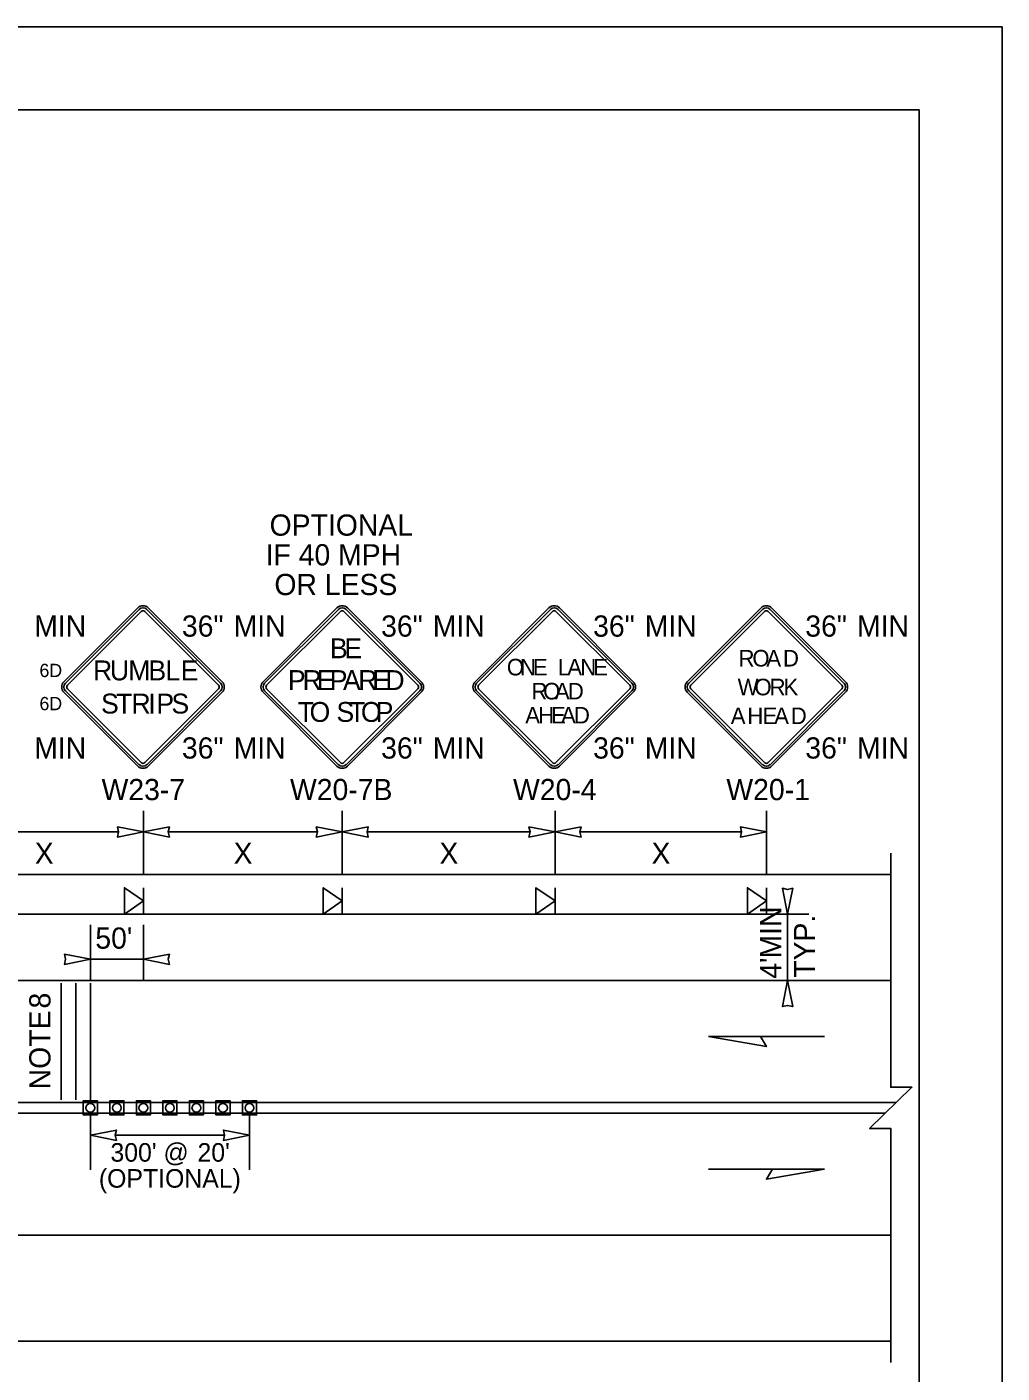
# Model space of a CAD drawing. Extents: x 99999.1 to 100095.7, y 99995 to 100010.7.
# Drawn here: x 100012.38 to 100016.06, y 100005.61 to 100010.69 of the extents above; entities that cross this region are included whole.
import ezdxf

# ---------------------------------------------------------------- set-up
doc = ezdxf.new("R2010")
doc.units = 0
for name, color, linetype in [('RD_ED_ShoulderPavedEdge', 7, 'Continuous'), ('RD_MK_LineDblYellowCenter', 7, 'Continuous'), ('RD_MK_LineEdgeWhite', 7, 'Continuous'), ('SH_GI_PlotLimits', 7, 'Continuous'), ('SH_GI_SheetBorder', 7, 'Continuous'), ('TR_SN_ConstructionSigns', 7, 'Continuous'), ('TR_WZ_PortableSignMountBlk-Org', 7, 'Continuous'), ('TR_WZ_TrafficCone', 7, 'Continuous'), ('TR_WZ_WorkZoneDetails', 7, 'Continuous'), ('TR_WZ_WorkZoneTextCurrent', 7, 'Continuous')]:
    doc.layers.add(name, color=color, linetype=linetype)

msp = doc.modelspace()

# ---------------------------------------------------------------- linework, layer by layer
at = {"layer": 'RD_ED_ShoulderPavedEdge'}
for p, q in [((100000.1076, 100007.4923), (100015.6424, 100007.4923)), ((100000.1076, 100005.7323), (100015.6424, 100005.7323))]:
    msp.add_line(p, q, dxfattribs=at)
at = {"layer": 'RD_MK_LineDblYellowCenter'}
for p, q in [((100012.2733, 100006.6323), (100015.6631, 100006.6323)), ((100012.2733, 100006.5923), (100015.6218, 100006.5923))]:
    msp.add_line(p, q, dxfattribs=at)
at = {"layer": 'RD_MK_LineEdgeWhite'}
for p, q in [((100000.1076, 100007.0923), (100015.6424, 100007.0923)), ((100000.1076, 100006.1323), (100015.6424, 100006.1323))]:
    msp.add_line(p, q, dxfattribs=at)
at = {"layer": 'SH_GI_PlotLimits'}
msp.add_lwpolyline([(99999.0625, 99999.6875), (100016.0625, 99999.6875), (100016.0625, 100010.6875), (99999.0625, 100010.6875)], close=True, dxfattribs=at)
at = {"layer": 'SH_GI_SheetBorder'}
for p, q in [((100000, 100010.375), (100015.75, 100010.375)), ((100015.75, 100010.375), (100015.75, 100000))]:
    msp.add_line(p, q, dxfattribs=at)
at = {"layer": 'TR_SN_ConstructionSigns'}
for p, q in [((100012.8019, 100008.4972), (100012.5235, 100008.2188)), ((100012.8075, 100008.4917), (100012.529, 100008.2132)), ((100013.1146, 100008.2132), (100012.8362, 100008.4917)), ((100013.1201, 100008.2188), (100012.8417, 100008.4972)), ((100013.5535, 100008.4972), (100013.275, 100008.2188)), ((100013.559, 100008.4917), (100013.2806, 100008.2132)), ((100013.8661, 100008.2132), (100013.5877, 100008.4917)), ((100013.8717, 100008.2188), (100013.5932, 100008.4972)), ((100014.3532, 100008.4972), (100014.0747, 100008.2188)), ((100014.3587, 100008.4917), (100014.0803, 100008.2132)), ((100014.6658, 100008.2132), (100014.3874, 100008.4917)), ((100014.6714, 100008.2188), (100014.3929, 100008.4972)), ((100015.1535, 100008.4972), (100014.875, 100008.2188)), ((100015.159, 100008.4917), (100014.8806, 100008.2132)), ((100015.4661, 100008.2132), (100015.1877, 100008.4917)), ((100015.4717, 100008.2188), (100015.1932, 100008.4972)), ((100012.5368, 100008.2055), (100012.8152, 100008.4839)), ((100012.8285, 100008.4839), (100013.1069, 100008.2055)), ((100013.2883, 100008.2055), (100013.5667, 100008.4839)), ((100013.58, 100008.4839), (100013.8584, 100008.2055)), ((100014.088, 100008.2055), (100014.3664, 100008.4839)), ((100014.3797, 100008.4839), (100014.6581, 100008.2055)), ((100014.8883, 100008.2055), (100015.1667, 100008.4839)), ((100015.18, 100008.4839), (100015.4584, 100008.2055)), ((100012.529, 100008.1845), (100012.8075, 100007.9061)), ((100012.8152, 100007.9138), (100012.5368, 100008.1923)), ((100013.1069, 100008.1923), (100012.8285, 100007.9138)), ((100012.8362, 100007.9061), (100013.1146, 100008.1845)), ((100013.2806, 100008.1845), (100013.559, 100007.9061)), ((100013.5667, 100007.9138), (100013.2883, 100008.1923)), ((100013.8584, 100008.1923), (100013.58, 100007.9138)), ((100013.5877, 100007.9061), (100013.8661, 100008.1845)), ((100014.0803, 100008.1845), (100014.3587, 100007.9061)), ((100014.3664, 100007.9138), (100014.088, 100008.1923)), ((100014.6581, 100008.1923), (100014.3797, 100007.9138)), ((100014.3874, 100007.9061), (100014.6658, 100008.1845)), ((100014.8806, 100008.1845), (100015.159, 100007.9061)), ((100015.1667, 100007.9138), (100014.8883, 100008.1923)), ((100015.4584, 100008.1923), (100015.18, 100007.9138)), ((100015.1877, 100007.9061), (100015.4661, 100008.1845)), ((100012.5235, 100008.179), (100012.8019, 100007.9006)), ((100012.8417, 100007.9006), (100013.1201, 100008.179)), ((100013.275, 100008.179), (100013.5535, 100007.9006)), ((100013.5932, 100007.9006), (100013.8717, 100008.179)), ((100014.0747, 100008.179), (100014.3532, 100007.9006)), ((100014.3929, 100007.9006), (100014.6714, 100008.179)), ((100014.875, 100008.179), (100015.1535, 100007.9006)), ((100015.1932, 100007.9006), (100015.4717, 100008.179))]:
    msp.add_line(p, q, dxfattribs=at)
for centre, radius, start, end in [((100012.8218, 100008.4773), 0.0281, 45, 135), ((100012.8218, 100008.4773), 0.0203, 45, 135), ((100013.5733, 100008.4773), 0.0281, 45, 135), ((100013.5733, 100008.4773), 0.0203, 45, 135), ((100014.373, 100008.4773), 0.0281, 45, 135), ((100014.373, 100008.4773), 0.0203, 45, 135), ((100015.1733, 100008.4773), 0.0281, 45, 135), ((100015.1733, 100008.4773), 0.0203, 45, 135), ((100012.8218, 100008.4773), 0.00937, 45, 135), ((100013.5733, 100008.4773), 0.00937, 45, 135), ((100014.373, 100008.4773), 0.00937, 45, 135), ((100015.1733, 100008.4773), 0.00937, 45, 135), ((100012.5434, 100008.1989), 0.0281, 135, 225), ((100012.5434, 100008.1989), 0.0203, 135, 225), ((100012.5434, 100008.1989), 0.00937, 135, 225), ((100013.1003, 100008.1989), 0.00937, 315, 45), ((100013.1003, 100008.1989), 0.0203, 315, 45), ((100013.1003, 100008.1989), 0.0281, 315, 45), ((100013.2949, 100008.1989), 0.0281, 135, 225), ((100013.2949, 100008.1989), 0.0203, 135, 225), ((100013.2949, 100008.1989), 0.00937, 135, 225), ((100013.8518, 100008.1989), 0.00937, 315, 45), ((100013.8518, 100008.1989), 0.0203, 315, 45), ((100013.8518, 100008.1989), 0.0281, 315, 45), ((100014.0946, 100008.1989), 0.0281, 135, 225), ((100014.0946, 100008.1989), 0.0203, 135, 225), ((100014.0946, 100008.1989), 0.00937, 135, 225), ((100014.6515, 100008.1989), 0.00937, 315, 45), ((100014.6515, 100008.1989), 0.0203, 315, 45), ((100014.6515, 100008.1989), 0.0281, 315, 45), ((100014.8949, 100008.1989), 0.0281, 135, 225), ((100014.8949, 100008.1989), 0.0203, 135, 225), ((100014.8949, 100008.1989), 0.00937, 135, 225), ((100015.4518, 100008.1989), 0.00937, 315, 45), ((100015.4518, 100008.1989), 0.0203, 315, 45), ((100015.4518, 100008.1989), 0.0281, 315, 45), ((100012.8218, 100007.9205), 0.0281, 225, 315), ((100012.8218, 100007.9205), 0.0203, 225, 315), ((100012.8218, 100007.9205), 0.00937, 225, 315), ((100013.5733, 100007.9205), 0.0281, 225, 315), ((100013.5733, 100007.9205), 0.0203, 225, 315), ((100013.5733, 100007.9205), 0.00937, 225, 315), ((100014.373, 100007.9205), 0.0281, 225, 315), ((100014.373, 100007.9205), 0.0203, 225, 315), ((100014.373, 100007.9205), 0.00937, 225, 315), ((100015.1733, 100007.9205), 0.0281, 225, 315), ((100015.1733, 100007.9205), 0.0203, 225, 315), ((100015.1733, 100007.9205), 0.00937, 225, 315)]:
    msp.add_arc(centre, radius, start, end, dxfattribs=at)
at = {"layer": 'TR_WZ_PortableSignMountBlk-Org'}
for p, q in [((100012.8233, 100007.4422), (100012.8233, 100007.3422)), ((100013.5733, 100007.4422), (100013.5733, 100007.3422)), ((100014.3761, 100007.4422), (100014.3761, 100007.3422)), ((100015.1733, 100007.4422), (100015.1733, 100007.3422))]:
    msp.add_line(p, q, dxfattribs=at)
for points in [[(100012.8233, 100007.3923), (100012.7515, 100007.3422), (100012.7515, 100007.4422)], [(100013.5733, 100007.3923), (100013.5015, 100007.3422), (100013.5015, 100007.4422)], [(100014.3761, 100007.3923), (100014.3042, 100007.3422), (100014.3042, 100007.4422)], [(100015.1733, 100007.3923), (100015.1015, 100007.3422), (100015.1015, 100007.4422)]]:
    msp.add_lwpolyline(points, close=True, dxfattribs=at)
at = {"layer": 'TR_WZ_TrafficCone'}
for points in [[(100012.65, 100006.5857), (100012.5967, 100006.5857), (100012.5967, 100006.639), (100012.65, 100006.639), (100012.65, 100006.5857)], [(100012.65, 100006.639), (100012.5967, 100006.639), (100012.5967, 100006.5857), (100012.65, 100006.5857), (100012.65, 100006.639)], [(100012.75, 100006.5857), (100012.6967, 100006.5857), (100012.6967, 100006.639), (100012.75, 100006.639), (100012.75, 100006.5857)], [(100012.75, 100006.639), (100012.6967, 100006.639), (100012.6967, 100006.5857), (100012.75, 100006.5857), (100012.75, 100006.639)], [(100012.85, 100006.5857), (100012.7967, 100006.5857), (100012.7967, 100006.639), (100012.85, 100006.639), (100012.85, 100006.5857)], [(100012.85, 100006.639), (100012.7967, 100006.639), (100012.7967, 100006.5857), (100012.85, 100006.5857), (100012.85, 100006.639)], [(100012.95, 100006.5857), (100012.8967, 100006.5857), (100012.8967, 100006.639), (100012.95, 100006.639), (100012.95, 100006.5857)], [(100012.95, 100006.639), (100012.8967, 100006.639), (100012.8967, 100006.5857), (100012.95, 100006.5857), (100012.95, 100006.639)], [(100013.05, 100006.5857), (100012.9967, 100006.5857), (100012.9967, 100006.639), (100013.05, 100006.639), (100013.05, 100006.5857)], [(100013.05, 100006.639), (100012.9967, 100006.639), (100012.9967, 100006.5857), (100013.05, 100006.5857), (100013.05, 100006.639)], [(100013.15, 100006.5857), (100013.0967, 100006.5857), (100013.0967, 100006.639), (100013.15, 100006.639), (100013.15, 100006.5857)], [(100013.15, 100006.639), (100013.0967, 100006.639), (100013.0967, 100006.5857), (100013.15, 100006.5857), (100013.15, 100006.639)], [(100013.25, 100006.5857), (100013.1967, 100006.5857), (100013.1967, 100006.639), (100013.25, 100006.639), (100013.25, 100006.5857)], [(100013.25, 100006.639), (100013.1967, 100006.639), (100013.1967, 100006.5857), (100013.25, 100006.5857), (100013.25, 100006.639)]]:
    msp.add_lwpolyline(points, dxfattribs=at)
for centre in [(100012.6233, 100006.6123), (100012.7233, 100006.6123), (100012.8233, 100006.6123), (100012.9233, 100006.6123), (100013.0233, 100006.6123), (100013.1233, 100006.6123), (100013.2233, 100006.6123)]:
    msp.add_circle(centre, 0.0167, dxfattribs=at)
at = {"layer": 'TR_WZ_WorkZoneDetails'}
for p, q in [((100012.8233, 100007.4923), (100012.8233, 100007.7323)), ((100013.5733, 100007.4923), (100013.5733, 100007.7323)), ((100014.3761, 100007.4923), (100014.3761, 100007.7323)), ((100015.1733, 100007.4921), (100015.1733, 100007.7323)), ((100012.1671, 100007.6523), (100012.7296, 100007.6523)), ((100012.9171, 100007.6523), (100013.4796, 100007.6523)), ((100013.6671, 100007.6523), (100014.2823, 100007.6523)), ((100014.4698, 100007.6523), (100015.0796, 100007.6523)), ((100012.0733, 100007.3422), (100015.1733, 100007.3422)), ((100015.1733, 100007.3422), (100015.3333, 100007.3422)), ((100015.2533, 100007.3422), (100015.2533, 100007.0923)), ((100012.6233, 100007.0923), (100012.6233, 100007.3023)), ((100012.8233, 100007.3023), (100012.8233, 100007.0923)), ((100012.6233, 100007.1723), (100012.8233, 100007.1723)), ((100012.5128, 100006.6423), (100012.5128, 100007.0823)), ((100012.5685, 100006.6423), (100012.5685, 100007.0823)), ((100012.6233, 100006.6423), (100012.6233, 100007.0823)), ((100015.1733, 100007.0923), (100015.3333, 100007.0923)), ((100015.1513, 100006.8816), (100015.3924, 100006.8816)), ((100012.6233, 100006.589), (100012.6233, 100006.379)), ((100013.2233, 100006.379), (100013.2233, 100006.589)), ((100013.1296, 100006.509), (100012.7171, 100006.509)), ((100015.1959, 100006.3816), (100014.9548, 100006.3816))]:
    msp.add_line(p, q, dxfattribs=at)
for points in [[(100012.8233, 100007.6523), (100012.7251, 100007.6331), (100012.7296, 100007.6523), (100012.7251, 100007.6716)], [(100012.8233, 100007.6523), (100012.9216, 100007.6331), (100012.9171, 100007.6523), (100012.9216, 100007.6716)], [(100013.5733, 100007.6523), (100013.4751, 100007.6331), (100013.4796, 100007.6523), (100013.4751, 100007.6716)], [(100013.5733, 100007.6523), (100013.6716, 100007.6331), (100013.6671, 100007.6523), (100013.6716, 100007.6716)], [(100014.3761, 100007.6523), (100014.2778, 100007.6331), (100014.2823, 100007.6523), (100014.2778, 100007.6716)], [(100014.3761, 100007.6523), (100014.4743, 100007.6331), (100014.4698, 100007.6523), (100014.4743, 100007.6716)], [(100015.1733, 100007.6523), (100015.0751, 100007.6331), (100015.0796, 100007.6523), (100015.0751, 100007.6716)], [(100015.2533, 100007.3422), (100015.2341, 100007.4405), (100015.2533, 100007.436), (100015.2726, 100007.4405)], [(100012.6233, 100007.1723), (100012.5251, 100007.1916), (100012.5296, 100007.1723), (100012.5251, 100007.1531)], [(100012.8233, 100007.1723), (100012.9216, 100007.1916), (100012.9171, 100007.1723), (100012.9216, 100007.1531)], [(100015.2533, 100007.0923), (100015.2341, 100006.9941), (100015.2533, 100006.9986), (100015.2726, 100006.9941)], [(100014.9548, 100006.8816), (100015.1736, 100006.843), (100015.1513, 100006.8816)], [(100012.6233, 100006.509), (100012.7216, 100006.4897), (100012.7171, 100006.509), (100012.7216, 100006.5283)], [(100013.2233, 100006.509), (100013.1251, 100006.4897), (100013.1296, 100006.509), (100013.1251, 100006.5283)], [(100015.3924, 100006.3816), (100015.1736, 100006.343), (100015.1959, 100006.3816)]]:
    msp.add_lwpolyline(points, close=True, dxfattribs=at)
msp.add_lwpolyline([(100015.6424, 100005.6523), (100015.6424, 100006.5349), (100015.5624, 100006.5349), (100015.7225, 100006.6898), (100015.6424, 100006.6898), (100015.6424, 100007.5723)], dxfattribs=at)

# ---------------------------------------------------------------- texts
at = {"layer": 'TR_SN_ConstructionSigns'}
for s, height, p in [('OPTIONAL', 0.08, (100013.2994, 100008.7694)), ('IF 40 MPH', 0.08, (100013.2843, 100008.6574)), ('OR LESS', 0.08, (100013.3175, 100008.5454)), ('B', 0.075, (100013.5271, 100008.3074)), ('E', 0.075, (100013.5814, 100008.3074)), ('R', 0.0625, (100015.0683, 100008.2762)), ('O', 0.0625, (100015.1204, 100008.2762)), ('A', 0.0625, (100015.1732, 100008.2762)), ('D', 0.0625, (100015.2359, 100008.2762)), ('6D', 0.05, (100012.4313, 100008.2364)), ('R', 0.075, (100012.6332, 100008.2239)), ('U', 0.075, (100012.697, 100008.2239)), ('M', 0.075, (100012.766, 100008.2239)), ('B', 0.075, (100012.8425, 100008.2239)), ('L', 0.075, (100012.9062, 100008.2239)), ('E', 0.075, (100012.964, 100008.2239)), ('O', 0.0625, (100014.1943, 100008.2426)), ('N', 0.0625, (100014.2437, 100008.2426)), ('E', 0.0625, (100014.2924, 100008.2426)), ('L', 0.0625, (100014.3868, 100008.2426)), ('A', 0.0625, (100014.4224, 100008.2426)), ('N', 0.0625, (100014.4712, 100008.2426)), ('E', 0.0625, (100014.5199, 100008.2426)), ('P', 0.075, (100013.3684, 100008.1874)), ('R', 0.075, (100013.4237, 100008.1874)), ('E', 0.075, (100013.4769, 100008.1874)), ('P', 0.075, (100013.5264, 100008.1874)), ('A', 0.075, (100013.5763, 100008.1874)), ('R', 0.075, (100013.6335, 100008.1874)), ('E', 0.075, (100013.6868, 100008.1874)), ('D', 0.075, (100013.7362, 100008.1874)), ('R', 0.0625, (100014.2868, 100008.152)), ('O', 0.0625, (100014.3312, 100008.152)), ('A', 0.0625, (100014.3755, 100008.152)), ('D', 0.0625, (100014.4243, 100008.152)), ('W', 0.0625, (100015.065, 100008.1676)), ('O', 0.0625, (100015.1282, 100008.1676)), ('R', 0.0625, (100015.1855, 100008.1676)), ('K', 0.0625, (100015.2379, 100008.1676)), ('6D', 0.05, (100012.4313, 100008.1114)), ('S', 0.075, (100012.6636, 100008.0989)), ('T', 0.075, (100012.7206, 100008.0989)), ('R', 0.075, (100012.7783, 100008.0989)), ('I', 0.075, (100012.8421, 100008.0989)), ('P', 0.075, (100012.8721, 100008.0989)), ('S', 0.075, (100012.9291, 100008.0989)), ('T', 0.075, (100013.4051, 100008.0674)), ('O', 0.075, (100013.4502, 100008.0674)), ('S', 0.075, (100013.5516, 100008.0674)), ('T', 0.075, (100013.5988, 100008.0674)), ('O', 0.075, (100013.6439, 100008.0674)), ('P', 0.075, (100013.6996, 100008.0674)), ('A', 0.0625, (100014.2637, 100008.0614)), ('H', 0.0625, (100014.3124, 100008.0614)), ('E', 0.0625, (100014.3612, 100008.0614)), ('A', 0.0625, (100014.3987, 100008.0614)), ('D', 0.0625, (100014.4474, 100008.0614)), ('A', 0.0625, (100015.039, 100008.0591)), ('H', 0.0625, (100015.1015, 100008.0591)), ('E', 0.0625, (100015.159, 100008.0591)), ('A', 0.0625, (100015.2027, 100008.0591)), ('D', 0.0625, (100015.2652, 100008.0591))]:
    msp.add_text(s, height=height, dxfattribs=at).set_placement(p)
for s, p in [('MIN', (100012.4114, 100008.3887)), ('36"', (100012.9686, 100008.3887)), ('MIN', (100013.1636, 100008.3887)), ('36"', (100013.7201, 100008.3887)), ('MIN', (100013.9151, 100008.3887)), ('36"', (100014.5198, 100008.3887)), ('MIN', (100014.7148, 100008.3887)), ('36"', (100015.3201, 100008.3887)), ('MIN', (100015.5151, 100008.3887)), ('MIN', (100012.4114, 100007.9291)), ('36"', (100012.9686, 100007.9291)), ('MIN', (100013.1636, 100007.9291)), ('36"', (100013.7201, 100007.9291)), ('MIN', (100013.9151, 100007.9291)), ('36"', (100014.5198, 100007.9291)), ('MIN', (100014.7148, 100007.9291)), ('36"', (100015.3201, 100007.9291)), ('MIN', (100015.5151, 100007.9291)), ('W23-7', (100012.6656, 100007.7723)), ('W20-7B', (100013.3763, 100007.7723)), ('W20-4', (100014.2176, 100007.7723)), ('W20-1', (100015.0224, 100007.7723))]:
    msp.add_text(s, height=0.08, rotation=360, dxfattribs=at).set_placement(p)
at = {"layer": 'TR_WZ_WorkZoneDetails'}
for s, p in [('8', (100012.4728, 100006.9868)), ('NOTE', (100012.4728, 100006.682))]:
    msp.add_text(s, height=0.08, rotation=90, dxfattribs=at).set_placement(p)
at = {"layer": 'TR_WZ_WorkZoneTextCurrent'}
for s, height, p in [('X', 0.08, (100012.4136, 100007.5323)), ('X', 0.08, (100013.1636, 100007.5323)), ('X', 0.08, (100013.94, 100007.5323)), ('X', 0.08, (100014.74, 100007.5323)), ("50'", 0.08, (100012.6421, 100007.2123)), ("300' @", 0.07, (100012.699, 100006.4093)), ("20'", 0.07, (100013.0274, 100006.4093)), ('(OPTIONAL)', 0.07, (100012.6553, 100006.3113))]:
    msp.add_text(s, height=height, dxfattribs=at).set_placement(p)
for s, p in [('MIN', (100015.2293, 100007.1754)), ('TYP.', (100015.3573, 100007.1026)), ("4'", (100015.2293, 100007.0989))]:
    msp.add_text(s, height=0.08, rotation=90, dxfattribs=at).set_placement(p)

doc.saveas('drawing.dxf')
